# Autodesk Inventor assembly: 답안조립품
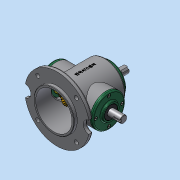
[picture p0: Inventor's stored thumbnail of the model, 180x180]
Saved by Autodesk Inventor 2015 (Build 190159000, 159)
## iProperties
Created: 2018-04
Part Number: 답안조립품
Document SubType Name: Assembly
Designer: Administrator
Author: Administrator
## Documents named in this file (16)
- C:\Users\Administrator\Desktop\480408V1012\답안조립품.iam
- C:\Users\Administrator\Desktop\480408V1012\메인 베벨기어.ipt
- C:\Users\Administrator\Desktop\480408V1012\메인 축.ipt
- 메인 축.ipt
- C:\Users\Administrator\Desktop\480408V1012\베어링 6203.ipt
- C:\Users\Administrator\Desktop\480408V1012\본체.ipt
- C:\Users\Administrator\Desktop\480408V1012\볼트 M4.ipt
- 볼트 M4.ipt
- C:\Users\Administrator\Desktop\480408V1012\서브 베벨기어.ipt
- C:\Users\Administrator\Desktop\480408V1012\서브 축.ipt
- 서브 축.ipt
- C:\Users\Administrator\Desktop\480408V1012\오일 실.ipt
- 오일 실.ipt
- C:\Users\Administrator\Desktop\480408V1012\커버.ipt
- C:\Users\Administrator\Desktop\480408V1012\키 4x4.ipt
- C:\Users\Administrator\Desktop\480408V1012\키 5x5.ipt
